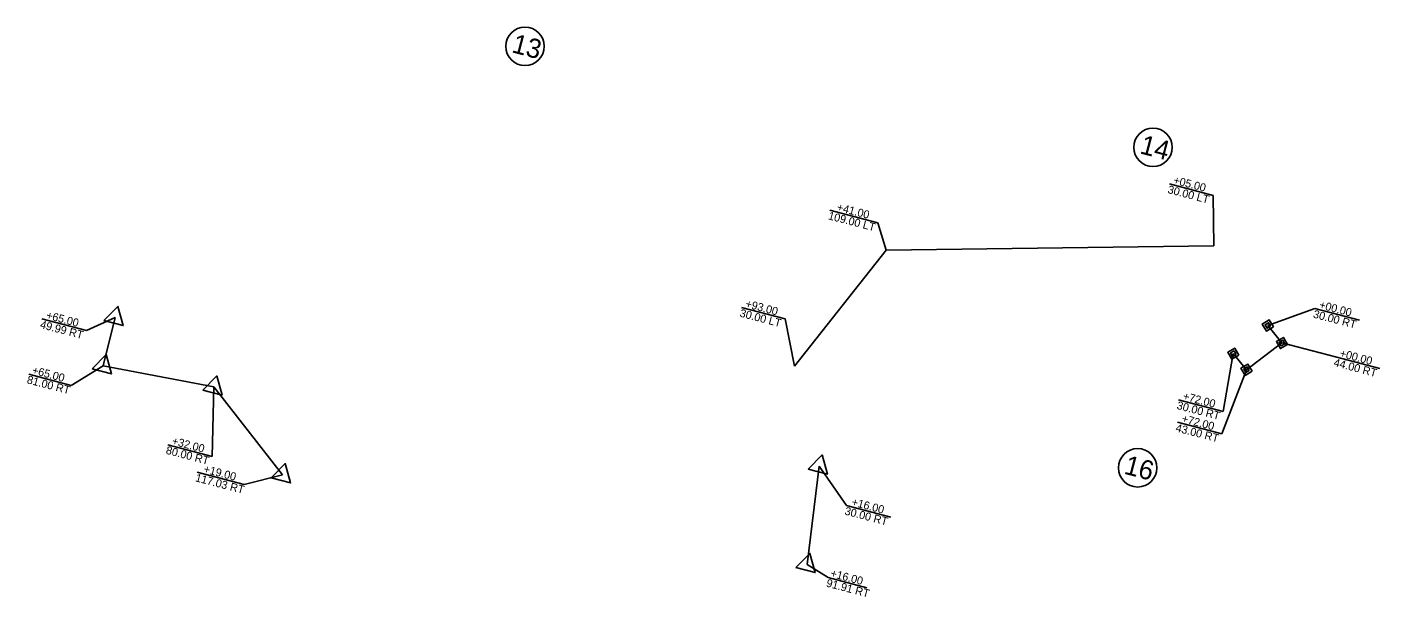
# Model space of a CAD drawing. Extents: x 1002576 to 1014655, y 551673 to 557994.
# Drawn here: x 1007891 to 1008737, y 551673 to 552029 of the extents above; entities that cross this region are included whole.
import ezdxf

# ---------------------------------------------------------------- set-up
doc = ezdxf.new("R2010")
doc.units = 0
for name, color, linetype in [('Exist Building', 7, 'Continuous'), ('Exist Guardrail', 7, 'Continuous'), ('Exist Hydro River Flow Arrow CELL', 7, 'Continuous'), ('Exist Hydro Stream or Body of Water', 7, 'Continuous'), ('Exist Roads EOP Text', 7, 'Continuous'), ('Exist Roads Soil', 7, 'Continuous'), ('Exist Roads Soil Text', 7, 'Continuous'), ('Exist Structure Major Deck Tunnel Box Culvert', 7, 'Continuous'), ('Exist Utilities Power Pole CELL', 7, 'Continuous')]:
    doc.layers.add(name, color=color, linetype=linetype)

msp = doc.modelspace()

# ---------------------------------------------------------------- linework, layer by layer
at = {"layer": 'Exist Building'}
for p, q in [((1008666.78, 551842.95), (1008675.58, 551832.06)), ((1008653.43, 551815.33), (1008675.58, 551832.06)), ((1008645.2, 551825.39), (1008653.43, 551815.33))]:
    msp.add_line(p, q, dxfattribs=at)
at = {"layer": 'Exist Guardrail'}
for p, q in [((1008370.94, 551817.54), (1008428.39, 551890.02)), ((1008428.39, 551890.02), (1008632.99, 551892.78))]:
    msp.add_line(p, q, dxfattribs=at)
at = {"layer": 'Exist Hydro River Flow Arrow CELL'}
for p, q in [((1007928.56, 551839.77), (1007900.79, 551847.04)), ((1007919.13, 551805.6), (1007892.52, 551812.56)), ((1008007.13, 551761.28), (1007979.36, 551768.55)), ((1008027.05, 551743.69), (1007997.77, 551751.35)), ((1008431.21, 551723.33), (1008403.44, 551730.6)), ((1008416.27, 551679.24), (1008391.97, 551685.6))]:
    msp.add_line(p, q, dxfattribs=at)
for points in [[(1007928.56, 551839.77), (1007946.48, 551847.95)], [(1007919.13, 551805.6), (1007939.05, 551817.84)], [(1008007.13, 551761.28), (1008008.22, 551804.58)], [(1008027.05, 551743.69), (1008051.02, 551749.78)], [(1008403.44, 551730.6), (1008386.46, 551755.15)], [(1008391.97, 551685.6), (1008378.84, 551693.71)]]:
    msp.add_lwpolyline(points, dxfattribs=at)
at = {"layer": 'Exist Hydro Stream or Body of Water'}
for p, q in [((1007946.48, 551847.95), (1007946.48, 551847.95)), ((1008666.78, 551842.95), (1008666.78, 551842.95)), ((1008675.58, 551832.06), (1008675.58, 551832.06)), ((1007939.05, 551817.84), (1007939.05, 551817.84)), ((1008645.2, 551825.39), (1008645.2, 551825.39)), ((1008653.43, 551815.33), (1008653.43, 551815.33)), ((1008008.22, 551804.58), (1008008.22, 551804.58)), ((1008051.02, 551749.78), (1008051.02, 551749.78)), ((1008386.46, 551755.15), (1008386.46, 551755.15)), ((1008378.84, 551693.71), (1008378.84, 551693.71))]:
    msp.add_line(p, q, dxfattribs=at)
for points in [[(1007939.52, 551846.05), (1007948.3, 551854.91), (1007951.61, 551842.88)], [(1007932.1, 551815.94), (1007940.88, 551824.8), (1007944.19, 551812.77)], [(1008001.26, 551802.68), (1008010.04, 551811.54), (1008013.35, 551799.51)], [(1008379.5, 551753.25), (1008388.28, 551762.12), (1008391.6, 551750.09)], [(1008044.07, 551747.88), (1008052.85, 551756.74), (1008056.16, 551744.71)], [(1008371.88, 551691.81), (1008380.66, 551700.68), (1008383.97, 551688.65)]]:
    msp.add_lwpolyline(points, close=True, dxfattribs=at)
at = {"layer": 'Exist Roads EOP Text'}
for p, q in [((1008723.95, 551846.29), (1008696.18, 551853.56)), ((1008736.81, 551816.04), (1008709.04, 551823.31)), ((1008638.79, 551789.27), (1008611.02, 551796.54)), ((1008638.07, 551775.26), (1008610.3, 551782.53))]:
    msp.add_line(p, q, dxfattribs=at)
for points in [[(1008696.18, 551853.56), (1008666.78, 551842.95)], [(1008709.04, 551823.31), (1008675.58, 551832.06)], [(1008638.79, 551789.27), (1008645.2, 551825.39)], [(1008638.07, 551775.26), (1008653.43, 551815.33)]]:
    msp.add_lwpolyline(points, dxfattribs=at)
at = {"layer": 'Exist Roads Soil'}
for p, q in [((1007946.48, 551847.95), (1007939.05, 551817.84)), ((1007939.05, 551817.84), (1008008.22, 551804.58)), ((1008008.22, 551804.58), (1008051.02, 551749.78)), ((1008378.84, 551693.71), (1008386.46, 551755.15))]:
    msp.add_line(p, q, dxfattribs=at)
at = {"layer": 'Exist Roads Soil Text'}
for p, q in [((1008632.52, 551924.22), (1008605.32, 551931.33)), ((1008423.05, 551907.15), (1008393.18, 551914.97)), ((1008365.14, 551847.05), (1008337.94, 551854.16))]:
    msp.add_line(p, q, dxfattribs=at)
for points in [[(1008632.52, 551924.22), (1008632.99, 551892.78)], [(1008423.05, 551907.15), (1008428.39, 551890.02)], [(1008365.14, 551847.05), (1008370.94, 551817.54)]]:
    msp.add_lwpolyline(points, dxfattribs=at)
at = {"layer": 'Exist Structure Major Deck Tunnel Box Culvert'}
for points in [[(1008670.27, 551842.04), (1008665.87, 551839.47), (1008663.3, 551843.86), (1008667.69, 551846.43)], [(1008668.52, 551842.5), (1008666.33, 551841.21), (1008665.04, 551843.41), (1008667.24, 551844.69)], [(1008679.07, 551831.15), (1008674.67, 551828.58), (1008672.1, 551832.97), (1008676.49, 551835.55)], [(1008648.68, 551824.48), (1008644.29, 551821.91), (1008641.72, 551826.3), (1008646.11, 551828.87)], [(1008646.94, 551824.94), (1008644.74, 551823.65), (1008643.46, 551825.85), (1008645.65, 551827.13)], [(1008677.32, 551831.61), (1008675.13, 551830.32), (1008673.84, 551832.52), (1008676.04, 551833.8)], [(1008656.91, 551814.42), (1008652.52, 551811.85), (1008649.95, 551816.24), (1008654.34, 551818.81)], [(1008655.17, 551814.87), (1008652.97, 551813.59), (1008651.69, 551815.78), (1008653.88, 551817.07)]]:
    msp.add_lwpolyline(points, close=True, dxfattribs=at)
at = {"layer": 'Exist Utilities Power Pole CELL'}
for p, q in [((1008202.62, 552017.31), (1008202.62, 552017.31)), ((1008595.01, 551954.2), (1008595.01, 551954.2)), ((1008585.43, 551754.11), (1008585.43, 551754.11))]:
    msp.add_line(p, q, dxfattribs=at)
for centre in [(1008202.62, 552017.31), (1008595.01, 551954.2), (1008585.43, 551754.11)]:
    msp.add_circle(centre, 12, dxfattribs=at)

# ---------------------------------------------------------------- texts
at = {"layer": 'Exist Hydro River Flow Arrow CELL'}
for s, p in [('49.99 RT', (1007899.3, 551841.46)), ('+65.00', (1007903.09, 551847.24)), ('81.00 RT', (1007891.04, 551806.98)), ('+65.00', (1007894.25, 551812.91)), ('80.00 RT', (1007977.87, 551762.97)), ('+32.00', (1007981.67, 551768.75)), ('117.03 RT', (1007996.28, 551745.77)), ('+19.00', (1008001.41, 551751.2)), ('+16.00', (1008406.32, 551730.65)), ('30.00 RT', (1008401.95, 551725.01)), ('91.91 RT', (1008390.49, 551680.02)), ('+16.00', (1008393.12, 551686.11))]:
    msp.add_text(s, height=5, rotation=345.33392, dxfattribs=at).set_placement(p)
at = {"layer": 'Exist Roads EOP Text'}
for s, p in [('30.00 RT', (1008694.7, 551847.97)), ('+00.00', (1008698.49, 551853.76)), ('+00.00', (1008711.35, 551823.51)), ('44.00 RT', (1008707.56, 551817.72)), ('+72.00', (1008613.33, 551796.74)), ('30.00 RT', (1008609.53, 551790.96)), ('+72.00', (1008612.61, 551782.73)), ('43.00 RT', (1008608.81, 551776.94))]:
    msp.add_text(s, height=5, rotation=345.33392, dxfattribs=at).set_placement(p)
at = {"layer": 'Exist Roads Soil Text'}
for s, p in [('30.00 LT', (1008603.84, 551925.75)), ('+05.00', (1008607.34, 551931.61)), ('109.00 LT', (1008391.7, 551909.38)), ('+41.00', (1008397.12, 551914.74)), ('30.00 LT', (1008336.46, 551848.58)), ('+93.00', (1008339.97, 551854.44))]:
    msp.add_text(s, height=5, rotation=345.33392, dxfattribs=at).set_placement(p)
at = {"layer": 'Exist Utilities Power Pole CELL'}
for s, p in [('13', (1008193.76, 552013.69)), ('14', (1008586.21, 551950.57)), ('16', (1008576.35, 551750.54))]:
    msp.add_text(s, height=12, rotation=345.33435, dxfattribs=at).set_placement(p)

doc.saveas('drawing.dxf')
